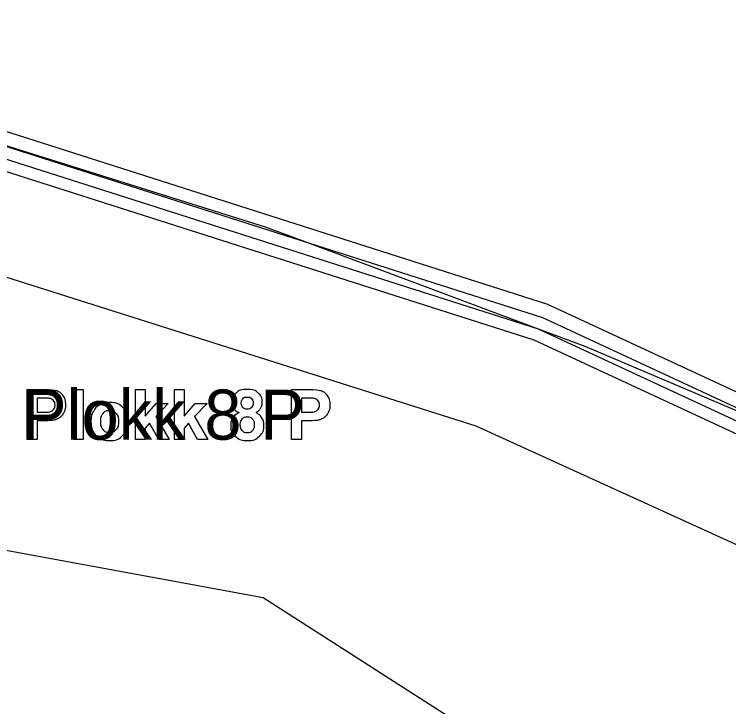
# Model space of a CAD drawing. Extents: x 532503 to 539665, y 6557663 to 6561526.
# Drawn here: x 537659.6 to 537779.4, y 6559649.9 to 6559766.1 of the extents above; entities that cross this region are included whole.
import ezdxf

# ---------------------------------------------------------------- set-up
doc = ezdxf.new("R2010")
doc.units = 0
for name, color, linetype in [('Default', 7, 'Continuous'), ('illumineerimisjooned', 7, 'Continuous'), ('PIIR', 7, 'Continuous'), ('Plokid', 7, 'Continuous'), ('Täide', 7, 'Continuous'), ('Veetase', 7, 'Continuous')]:
    doc.layers.add(name, color=color, linetype=linetype)

msp = doc.modelspace()

# ---------------------------------------------------------------- linework, layer by layer
at = {"layer": 'Default'}
msp.add_lwpolyline([(537470.8, 6559750.72), (537596.15, 6559761.6), (537596.15, 6559761.6), (537637.63, 6559750.4), (537658, 6559744.14), (537701.62, 6559730.4), (537705.43, 6559729.02), (537718.89, 6559723.97), (537747.42, 6559713.34), (537755.24, 6559710.4), (537786.09, 6559697.32), (537802.07, 6559690.4), (537824.66, 6559679.52), (537844.13, 6559670.4), (537875.25, 6559654), (537897.46, 6559668.25)], dxfattribs=at)
at = {"layer": 'illumineerimisjooned'}
msp.add_lwpolyline([(537335, 6559734.24), (537596.35, 6559763.64), (537748.15, 6559715.21), (537873.25, 6559657.14)], dxfattribs=at)
at = {"layer": 'PIIR'}
msp.add_lwpolyline([(537333, 6559732.01), (537596.15, 6559761.6), (537747.42, 6559713.34), (537875.25, 6559654)], dxfattribs=at)
at = {"layer": 'Plokid'}
for points in [[(537337.4, 6559736.93), (537596.59, 6559766.08), (537749.02, 6559717.45), (537870.85, 6559660.9)], [(537337.4, 6559730.49), (537595.95, 6559759.57), (537746.69, 6559711.48), (537873.25, 6559652.73)], [(537661.7, 6559694.72), (537661.7, 6559703.12), (537664.42, 6559703.12)], [(537669.52, 6559694.72), (537669.52, 6559703.12), (537671.13, 6559703.12), (537671.13, 6559694.72), (537669.52, 6559694.72)], [(537679.89, 6559694.72), (537679.89, 6559703.12), (537681.5, 6559703.12), (537681.5, 6559698.66), (537683.38, 6559700.81), (537685.37, 6559700.81), (537683.29, 6559698.58), (537685.51, 6559694.72), (537683.78, 6559694.72), (537682.25, 6559697.46), (537681.5, 6559696.67), (537681.5, 6559694.72), (537679.89, 6559694.72)], [(537686.41, 6559694.72), (537686.41, 6559703.12), (537688.03, 6559703.12), (537688.03, 6559698.66), (537689.91, 6559700.81), (537691.89, 6559700.81), (537689.81, 6559698.58), (537692.04, 6559694.72), (537690.3, 6559694.72), (537688.77, 6559697.46), (537688.03, 6559696.67), (537688.03, 6559694.72), (537686.41, 6559694.72)], [(537706.05, 6559694.72), (537706.05, 6559703.12), (537708.77, 6559703.12)], [(537663.4, 6559701.7), (537663.4, 6559699.31), (537664.32, 6559699.31)], [(537664.21, 6559701.7), (537663.4, 6559701.7)], [(537707.75, 6559701.7), (537707.75, 6559699.31), (537708.67, 6559699.31)], [(537708.56, 6559701.7), (537707.75, 6559701.7)], [(537664.5, 6559697.89), (537663.4, 6559697.89), (537663.4, 6559694.72), (537661.7, 6559694.72)], [(537708.85, 6559697.89), (537707.75, 6559697.89), (537707.75, 6559694.72), (537706.05, 6559694.72)]]:
    msp.add_lwpolyline(points, dxfattribs=at)
for points in [[(537664.42, 6559703.12), (537665.97, 6559703.12), (537666.44, 6559702.99), (537667.16, 6559702.8), (537667.65, 6559702.17), (537668.13, 6559701.54), (537668.13, 6559700.53), (537668.13, 6559699.76), (537667.85, 6559699.23), (537667.57, 6559698.71), (537667.14, 6559698.41), (537666.71, 6559698.11), (537666.26, 6559698.01), (537665.65, 6559697.89), (537664.5, 6559697.89)], [(537697.29, 6559699.25), (537696.66, 6559699.52), (537696.38, 6559699.98), (537696.09, 6559700.44), (537696.09, 6559700.99), (537696.09, 6559701.93), (537696.75, 6559702.54), (537697.41, 6559703.15), (537698.62, 6559703.15), (537699.81, 6559703.15), (537700.48, 6559702.54), (537701.14, 6559701.93), (537701.14, 6559700.99), (537701.14, 6559700.4), (537700.83, 6559699.95), (537700.53, 6559699.49), (537699.98, 6559699.25), (537700.68, 6559698.97), (537701.04, 6559698.43), (537701.41, 6559697.89), (537701.41, 6559697.19), (537701.41, 6559696.03), (537700.66, 6559695.3), (537699.92, 6559694.57), (537698.69, 6559694.57), (537697.54, 6559694.57), (537696.78, 6559695.17), (537695.88, 6559695.88), (537695.88, 6559697.12), (537695.88, 6559697.8), (537696.22, 6559698.37), (537696.56, 6559698.94), (537697.29, 6559699.25)], [(537708.77, 6559703.12), (537710.32, 6559703.12), (537710.79, 6559702.99), (537711.51, 6559702.8), (537712, 6559702.17), (537712.48, 6559701.54), (537712.48, 6559700.53), (537712.48, 6559699.76), (537712.2, 6559699.23), (537711.92, 6559698.71), (537711.49, 6559698.41), (537711.06, 6559698.11), (537710.61, 6559698.01), (537710, 6559697.89), (537708.85, 6559697.89)], [(537664.32, 6559699.31), (537665.33, 6559699.31), (537665.66, 6559699.44), (537666, 6559699.57), (537666.19, 6559699.85), (537666.39, 6559700.14), (537666.39, 6559700.51), (537666.39, 6559700.97), (537666.12, 6559701.27), (537665.85, 6559701.57), (537665.43, 6559701.64), (537665.13, 6559701.7), (537664.21, 6559701.7)], [(537697.62, 6559700.87), (537697.62, 6559700.39), (537697.89, 6559700.12), (537698.16, 6559699.85), (537698.62, 6559699.85), (537699.08, 6559699.85), (537699.35, 6559700.12), (537699.63, 6559700.4), (537699.63, 6559700.88), (537699.63, 6559701.33), (537699.35, 6559701.6), (537699.08, 6559701.87), (537698.63, 6559701.87), (537698.17, 6559701.87), (537697.89, 6559701.6), (537697.62, 6559701.32), (537697.62, 6559700.87)], [(537708.67, 6559699.31), (537709.68, 6559699.31), (537710.01, 6559699.44), (537710.35, 6559699.57), (537710.54, 6559699.85), (537710.74, 6559700.14), (537710.74, 6559700.51), (537710.74, 6559700.97), (537710.47, 6559701.27), (537710.2, 6559701.57), (537709.78, 6559701.64), (537709.48, 6559701.7), (537708.56, 6559701.7)], [(537672.4, 6559697.85), (537672.4, 6559698.65), (537672.79, 6559699.4), (537673.19, 6559700.15), (537673.91, 6559700.55), (537674.64, 6559700.94), (537675.54, 6559700.94), (537676.92, 6559700.94), (537677.8, 6559700.05), (537678.68, 6559699.15), (537678.68, 6559697.78), (537678.68, 6559696.4), (537677.79, 6559695.49), (537676.9, 6559694.58), (537675.55, 6559694.58), (537674.71, 6559694.58), (537673.95, 6559694.96), (537673.19, 6559695.34), (537672.79, 6559696.07), (537672.4, 6559696.8), (537672.4, 6559697.85)], [(537674.05, 6559697.76), (537674.05, 6559696.86), (537674.48, 6559696.38), (537674.91, 6559695.9), (537675.54, 6559695.9), (537676.17, 6559695.9), (537676.6, 6559696.38), (537677.03, 6559696.86), (537677.03, 6559697.77), (537677.03, 6559698.67), (537676.6, 6559699.15), (537676.17, 6559699.63), (537675.54, 6559699.63), (537674.91, 6559699.63), (537674.48, 6559699.15), (537674.05, 6559698.67), (537674.05, 6559697.76)], [(537697.47, 6559697.28), (537697.47, 6559696.61), (537697.81, 6559696.24), (537698.15, 6559695.86), (537698.66, 6559695.86), (537699.16, 6559695.86), (537699.49, 6559696.22), (537699.81, 6559696.58), (537699.81, 6559697.26), (537699.81, 6559697.85), (537699.48, 6559698.21), (537699.15, 6559698.57), (537698.64, 6559698.57), (537698.05, 6559698.57), (537697.76, 6559698.16), (537697.47, 6559697.75), (537697.47, 6559697.28)]]:
    msp.add_open_spline(points, degree=3, dxfattribs=at)
at = {"layer": 'Täide'}
msp.add_lwpolyline([(537303.91, 6559646.73), (537332.99, 6559646), (537596.15, 6559687.6), (537701.31, 6559668.24), (537759.9, 6559630.65), (537816.72, 6559549.2), (537847.4, 6559524.13), (537875.25, 6559518), (537897.46, 6559518)], dxfattribs=at)
msp.add_lwpolyline([(537303.91, 6559646.73), (537332.99, 6559646), (537596.15, 6559687.6), (537701.31, 6559668.24), (537759.9, 6559630.65), (537816.72, 6559549.2), (537847.4, 6559524.13), (537875.25, 6559518), (537897.46, 6559518)], dxfattribs=at)
msp.add_lwpolyline([(537303.91, 6559646.73), (537332.99, 6559646), (537596.15, 6559687.6), (537701.31, 6559668.24), (537759.9, 6559630.65), (537816.72, 6559549.2), (537847.4, 6559524.13), (537875.25, 6559518), (537897.46, 6559518)], dxfattribs=at)
at = {"layer": 'Veetase'}
msp.add_lwpolyline([(537897.46, 6559630.11), (537875.25, 6559634), (537737.03, 6559696.96), (537596.15, 6559741.6), (537333, 6559712), (537303.91, 6559709.89)], dxfattribs=at)

# ---------------------------------------------------------------- texts
at = {"layer": 'Plokid'}
msp.add_text('Plokk 8 P', height=8.4, dxfattribs=at).set_placement((537660.84, 6559694.72))

doc.saveas('drawing.dxf')
